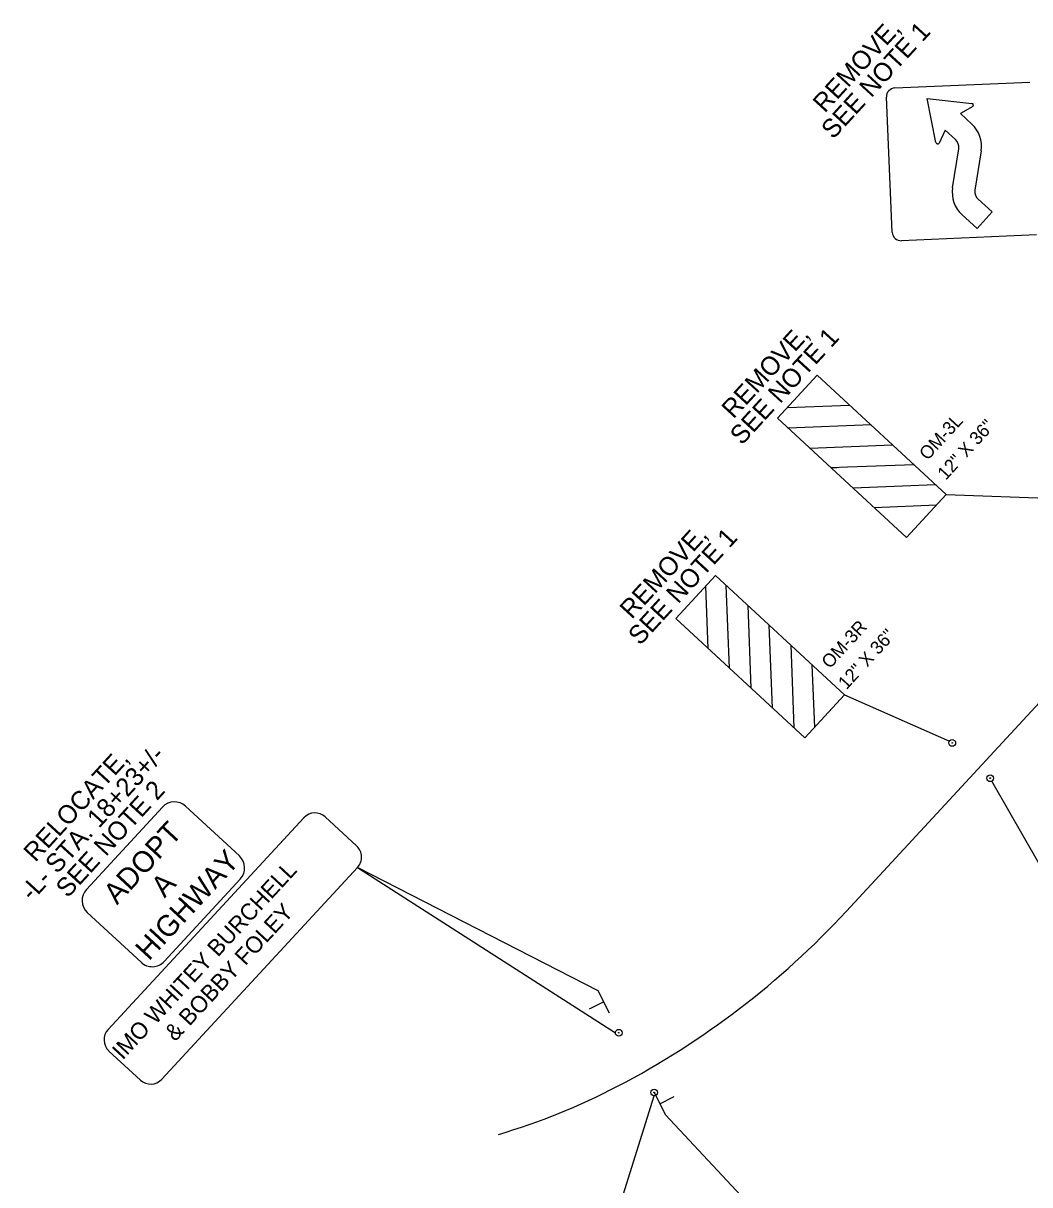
# Model space of a CAD drawing. Extents: x 1768295 to 1769615, y 998972 to 1001024.
# Drawn here: x 1768295 to 1768947, y 999896 to 1000648 of the extents above; entities that cross this region are included whole.
import ezdxf

# ---------------------------------------------------------------- set-up
doc = ezdxf.new("R2010")
doc.units = 0
for name, color, linetype in [('_CIVIL_CONSTRUCTION', 7, 'Continuous'), ('GSOUTLINE', 7, 'Continuous'), ('NonPlottingEle_dp', 7, 'Continuous'), ('PlotBorder_dp', 7, 'Continuous'), ('SheetBorder_dp', 7, 'Continuous'), ('SheetLines_dp', 7, 'Continuous'), ('SheetLinesMisc2_dp', 7, 'Continuous'), ('TextMinor', 7, 'Continuous'), ('TextMisc', 7, 'Continuous')]:
    doc.layers.add(name, color=color, linetype=linetype)

msp = doc.modelspace()

# ---------------------------------------------------------------- linework, layer by layer
at = {"layer": '_CIVIL_CONSTRUCTION'}
msp.add_line((1768828.51, 1000072.87), (1769100.08, 1000366.66), dxfattribs=at)
for centre, radius, start, end in [((1768427.56, 1000443.48), 546, 297.54772, 317.25123), ((1768480.75, 1000341.52), 431, 286.47443, 297.54772)]:
    msp.add_arc(centre, radius, start, end, dxfattribs=at)
at = {"layer": 'GSOUTLINE'}
for centre, radius in [((1768897.19, 1000181.93), 2.18), ((1768897.19, 1000181.93), 0.24), ((1768921.75, 1000159.05), 2.18), ((1768921.75, 1000159.05), 0.24), ((1768680.92, 999994.12), 2.18), ((1768680.92, 999994.12), 0.24), ((1768703.91, 999955.34), 2.18), ((1768703.91, 999955.34), 0.24)]:
    msp.add_circle(centre, radius, dxfattribs=at)
at = {"layer": 'NonPlottingEle_dp'}
for p, q in [((1768674.88, 1000006.76), (1768667.6, 1000021.23)), ((1768671.21, 1000014.06), (1768661.84, 1000009.34)), ((1768703.91, 999955.34), (1768711.19, 999940.87)), ((1768707.58, 999948.05), (1768716.96, 999952.77))]:
    msp.add_line(p, q, dxfattribs=at)
at = {"layer": 'PlotBorder_dp'}
for points in [[(1768335.75, 1000087.03), (1768385.02, 1000140.33)], [(1768400.09, 1000140.93), (1768434.94, 1000108.71)], [(1768435.53, 1000093.65), (1768386.25, 1000040.34)], [(1768371.19, 1000039.75), (1768336.34, 1000071.97)]]:
    msp.add_lwpolyline(points, dxfattribs=at)
for centre, start, end in [((1768392.85, 1000133.1), 47.25123, 137.25123), ((1768427.7, 1000100.89), 317.25123, 47.25123), ((1768343.58, 1000079.79), 137.25123, 227.25123), ((1768378.43, 1000047.58), 227.25123, 317.25123)]:
    msp.add_arc(centre, 10.66, start, end, dxfattribs=at)
at = {"layer": 'SheetBorder_dp'}
for p, q in [((1768809.66, 1000420.27), (1768783.88, 1000392.38)), ((1768893.32, 1000342.94), (1768809.66, 1000420.27)), ((1768790.32, 1000399.36), (1768830.57, 1000400.94)), ((1768783.88, 1000392.38), (1768818.84, 1000360.07)), ((1768844.52, 1000388.05), (1768790.85, 1000385.94)), ((1768804.79, 1000373.05), (1768858.46, 1000375.16)), ((1768829.28, 1000360.58), (1768818.74, 1000360.16)), ((1768818.84, 1000360.07), (1768867.54, 1000315.05)), ((1768872.4, 1000362.27), (1768829.28, 1000360.58)), ((1768832.68, 1000347.27), (1768886.35, 1000349.38)), ((1768867.54, 1000315.05), (1768893.32, 1000342.94)), ((1768886.88, 1000335.97), (1768846.62, 1000334.38))]:
    msp.add_line(p, q, dxfattribs=at)
for points in [[(1768821.41, 1000360.27), (1768818.74, 1000360.16)], [(1768822.43, 1000360.31), (1768821.41, 1000360.27)]]:
    msp.add_lwpolyline(points, dxfattribs=at)
at = {"layer": 'SheetLines_dp'}
for p, q in [((1768880.88, 1000599.64), (1768909.95, 1000596.47)), ((1768886.64, 1000571.03), (1768880.88, 1000599.64)), ((1768910.43, 1000594.43), (1768902.43, 1000589.81)), ((1768902.43, 1000589.81), (1768909.8, 1000583.06)), ((1768892.62, 1000579.1), (1768888.7, 1000570.71)), ((1768899.3, 1000572.98), (1768892.62, 1000579.1)), ((1768897.38, 1000541.66), (1768901.37, 1000566.99)), ((1768915.9, 1000565.65), (1768911.83, 1000540.23)), ((1768913.98, 1000534.32), (1768922.97, 1000526.08)), ((1768913.23, 1000515.46), (1768903.47, 1000524.41)), ((1768922.97, 1000526.08), (1768913.23, 1000515.46)), ((1768893.32, 1000342.94), (1769044.13, 1000337.32)), ((1768827.31, 1000213.13), (1768895.38, 1000183.15)), ((1768976.57, 1000063.08), (1768922.91, 1000157.21)), ((1768511.53, 1000101.22), (1768678.74, 999994.12)), ((1768668.04, 999839.46), (1768703.91, 999953.16))]:
    msp.add_line(p, q, dxfattribs=at)
for points in [[(1768859.97, 1000606.47), (1768947.45, 1000610.28)], [(1768858.26, 1000512.96), (1768854.45, 1000600.44)], [(1768951.76, 1000511.25), (1768864.29, 1000507.44)]]:
    msp.add_lwpolyline(points, dxfattribs=at)
for centre, radius, start, end in [((1768860.23, 1000600.69), 5.78, 92.48164, 137.48815), ((1768860.23, 1000600.69), 5.78, 137.48815, 182.49467), ((1768909.8, 1000595.33), 1.1, 304.92499, 83.58688), ((1768896.71, 1000568.7), 19.42, 351.07203, 47.49467), ((1768887.75, 1000571.26), 1.1, 191.40245, 330.06435), ((1768894.8, 1000568.07), 6.64, 351.07215, 47.49467), ((1768916.57, 1000538.67), 19.42, 171.07203, 227.49467), ((1768918.46, 1000539.21), 6.64, 171.07187, 227.49467), ((1768864.04, 1000513.22), 5.78, 182.49467, 272.49467)]:
    msp.add_arc(centre, radius, start, end, dxfattribs=at)
at = {"layer": 'SheetLinesMisc2_dp'}
for points in [[(1768349.79, 999996.22), (1768476.69, 1000133.42)], [(1768490.64, 1000133.97), (1768510.98, 1000115.17)], [(1768511.53, 1000101.22), (1768384.67, 999963.99)], [(1768370.72, 999963.44), (1768350.38, 999982.24)]]:
    msp.add_lwpolyline(points, dxfattribs=at)
for centre, start, end in [((1768483.94, 1000126.72), 47.25123, 137.25123), ((1768504.28, 1000107.92), 317.24983, 47.25123), ((1768357.04, 999989.53), 137.25123, 227.25123), ((1768377.42, 999970.68), 227.25123, 317.24983)]:
    msp.add_arc(centre, 9.87, start, end, dxfattribs=at)
at = {"layer": 'TextMinor'}
for p, q in [((1768667.6, 1000021.23), (1768511.53, 1000101.22)), ((1768874.75, 999766.24), (1768711.19, 999940.87))]:
    msp.add_line(p, q, dxfattribs=at)
at = {"layer": 'TextMisc'}
for p, q in [((1768717.86, 1000262.57), (1768743.64, 1000290.46)), ((1768743.64, 1000290.46), (1768827.31, 1000213.13)), ((1768737.2, 1000283.49), (1768738.78, 1000243.24)), ((1768752.73, 1000230.35), (1768750.61, 1000284.02)), ((1768764.56, 1000271.13), (1768766.67, 1000217.46)), ((1768801.53, 1000185.24), (1768717.86, 1000262.57)), ((1768780.61, 1000204.57), (1768778.5, 1000258.24)), ((1768792.45, 1000245.35), (1768794.56, 1000191.68)), ((1768807.97, 1000192.21), (1768806.39, 1000232.46)), ((1768827.31, 1000213.13), (1768801.53, 1000185.24))]:
    msp.add_line(p, q, dxfattribs=at)

# ---------------------------------------------------------------- texts
at = {"layer": 'PlotBorder_dp'}
for s, height, p in [('ADOPT', 13.715, (1768355.6, 1000076.51)), ('HIGHWAY', 13.715, (1768376.3, 1000040.24)), ('A', 13.71, (1768386.42, 1000081.05))]:
    msp.add_text(s, height=height, rotation=47.25123, dxfattribs=at).set_placement(p)
at = {"layer": 'SheetLines_dp'}
for s, p in [('OM-3L', (1768881.17, 1000364.62)), ('12" X 36"', (1768892.99, 1000351.85)), ('OM-3R', (1768817.79, 1000229.57)), ('12" X 36"', (1768828.6, 1000216.04))]:
    msp.add_text(s, height=8.515, rotation=47.49467, dxfattribs=at).set_placement(p)
at = {"layer": 'SheetLinesMisc2_dp'}
for s, p in [('IMO WHITEY BURCHELL', (1768359.32, 999976.02)), ('& BOBBY FOLEY', (1768393.31, 999987.96))]:
    msp.add_text(s, height=10.728, rotation=47.25123, dxfattribs=at).set_placement(p)
at = {"layer": 'TextMinor'}
for s, p in [('  REMOVE,', (1768808.52, 1000583.21)), ('SEE NOTE 1', (1768819.96, 1000572.72)), ('  REMOVE,', (1768749.32, 1000384.94)), ('SEE NOTE 1', (1768760.77, 1000374.45)), ('  REMOVE,', (1768683.31, 1000255.13)), ('SEE NOTE 1', (1768694.76, 1000244.64)), ('-L- STA. 18+23+/-', (1768300.53, 1000078.87)), ('RELOCATE,', (1768302.73, 1000104.13)), ('SEE NOTE 2', (1768323.65, 1000080.99))]:
    msp.add_text(s, height=12, rotation=47.49467, dxfattribs=at).set_placement(p)

doc.saveas('drawing.dxf')
